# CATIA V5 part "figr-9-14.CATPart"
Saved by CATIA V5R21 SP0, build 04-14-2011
Part number: Part2
Bounding box of the stored display mesh (mm): x -33.329 to 47.777, y -126.495 to 121.369, z -47.545 to 64.906
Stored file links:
  D:\CATIA V5R21 E-RESOURCES\CATIA-V5R21\catia-v5r21-prt\c09-catia-v5r20-prt\c09-catia-v5r21-figr-9-14.CATPart
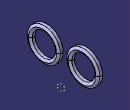
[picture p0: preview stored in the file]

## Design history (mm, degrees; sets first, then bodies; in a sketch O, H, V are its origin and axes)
Body1 (main body)
  Sketch1 on yz-plane, origin (0, 0, 0), H (0, 1, 0), V (0, 0, 1)
    circle A1 centre (-70.2613, 8.6726) radius 37.6716
    circle A2 centre (65.3061, 8.6726) radius 37.5
    radius A2 = 37.5
    radius A1 = 37.6716
  Plane1: type Angle, RefPlane yz-plane, Direction Sketch1.V, Angle 10
  Plane2: type Offset, RefPlane Plane1, Offset 55
  Sketch2 on Plane2, origin (44.5537, 64.0556, 0), H (-0.1736, 0.9848, 0), V (0, 0, 1)
    point P1 (-10.3597, -23.8575)
    point P2 (-2.157, -28.5933)
    point P3 (-2.157, -19.1216)
    point P4 (-10.3597, -14.3858)
    point P5 (-18.5625, -19.1216)
    point P6 (-18.5625, -28.5933)
    point P7 (-10.3597, -33.3292)
    point P8 (-2.157, -23.8575)
    line L1 (-2.157, -28.5933) -> (-2.157, -19.1216)
    line L2 (-2.157, -19.1216) -> (-10.3597, -14.3858)
    line L3 (-10.3597, -14.3858) -> (-18.5625, -19.1216)
    line L4 (-18.5625, -19.1216) -> (-18.5625, -28.5933)
    line L5 (-18.5625, -28.5933) -> (-10.3597, -33.3292)
    line L6 (-10.3597, -33.3292) -> (-2.157, -28.5933)
    construction line L7 (-10.3597, -23.8575) -> (-2.157, -23.8575)
    construction circle A1 centre (-10.3597, -23.8575) radius 9.4717
    construction arc A2 centre (-18.5625, -28.5933) radius 9.4717 from (-18.5625, -19.1216) to (-10.3597, -33.3292) cw
    construction arc A3 centre (-2.157, -19.1216) radius 9.4717 from (-10.3597, -14.3858) to (-2.157, -28.5933) ccw
    horizontal: L7 H
    coincidence: A1 P2, A1 P3, A1 P4, A1 P5, A1 P6, A1 P7, A2 P1, A3 P1
    midpoint: P8 L1
    parallelism: L1 L4
  Rib1: profile Sketch2, centre curve Sketch1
